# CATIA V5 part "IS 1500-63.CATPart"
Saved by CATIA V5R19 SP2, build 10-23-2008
Part number: IS 1500-63
Bounding box of the stored display mesh (mm): x -37.351 to 37.351, y -37.351 to 37.351, z 0 to 237
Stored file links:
  C:\Users\Bora\Desktop\3D Katı model\IS serisi\IS 1500\IS 1500-63.CATPart
  C:\Program Files\Dassault Systemes\B19\intel_a\reffiles\standard\MetricThickPitch.txt
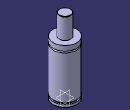
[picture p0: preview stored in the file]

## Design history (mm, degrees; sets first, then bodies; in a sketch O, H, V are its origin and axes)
Body1 (main body)
  Sketch1 on yz-plane, origin (0, 0, 0), H (0, 1, 0), V (0, 0, 1)
    point P1 (37.5, 155.5)
    point P4 (37.5, 150.5)
    point P7 (18, 236)
    point P9 (18, 236)
    point P13 (37.5, 155.5)
    point P14 (37.5, 150.5)
    line L1 (37.5, 155.5) -> (37.5, 171)
    line L2 (37.5, 13) -> (37.5, 150.5)
    line L3 (33.5, 13) -> (33.5, 8)
    arc A1 centre (17, 236) radius 1 from (18, 236) to (17, 237) ccw
    line L4 (18, 236) -> (18, 171)
    line L5 (37.5, 0) -> (37.5, 8)
    arc A2 centre (37.5, 153) radius 2.5 from (37.5, 155.5) to (37.5, 150.5) ccw
    line L6 (17, 237) -> (0, 237)
    line L7 (18, 171) -> (37.5, 171)
    line L8 (0, 0) -> (37.5, 0)
    line L9 (33.5, 8) -> (37.5, 8)
    line L10 (33.5, 13) -> (37.5, 13)
    horizontal: L6 H, L7 H, L8 H, L9 H, L10 H
    coincidence: P1 P13, P4 P14, P7 P9
  Shaft1: profile Sketch1, axis Sketch1.V, angle 360
  Sketch2 on face of Shaft1 from Sketch1.L8, origin (0, 0, 0), H (1, 0, 0), V (0, -1, 0)
    point P1 (20, 0)
    distance P1 V = 20
  Hole1: placed by Sketch2, at (20, 0, 0) direction (0, 0, 1), diameter 6.647, depth 13, threaded "M8", thread diameter 8, thread depth 13, pitch 1.25
  CircPattern1: of Hole1, instances 4, angular step 90, axis from xy-plane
